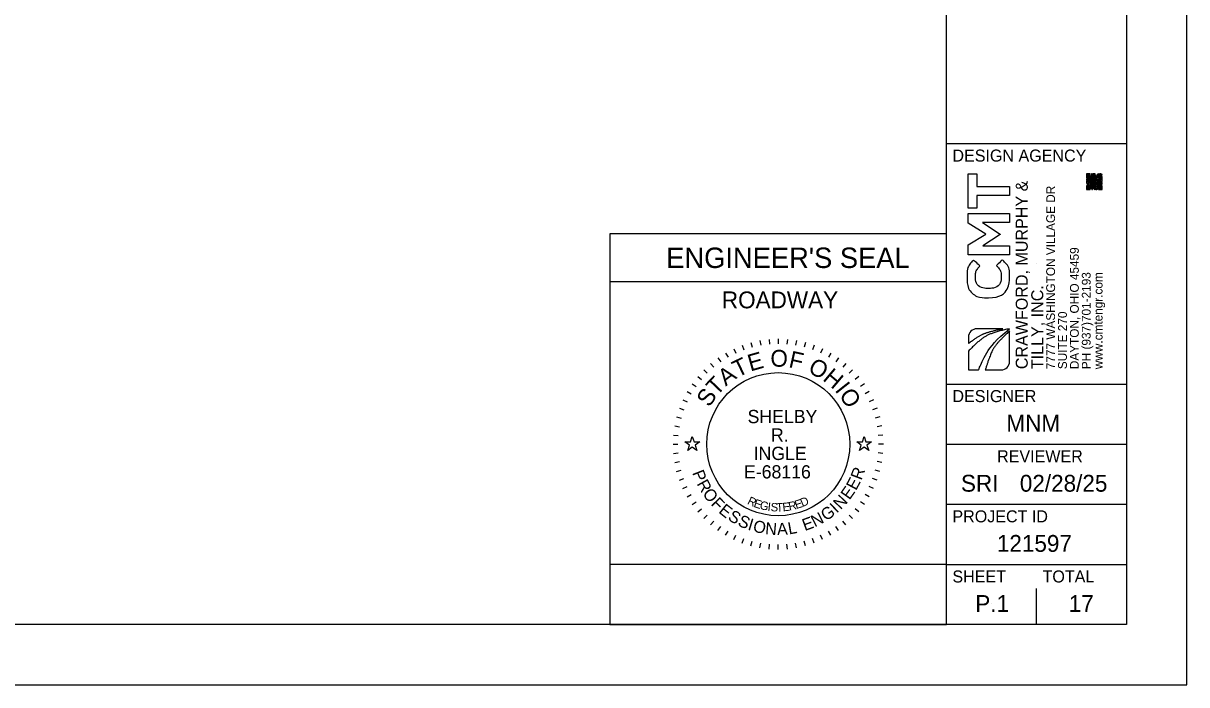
# Model space of a CAD drawing. Extents: x 0 to 42, y 0 to 22.
# Drawn here: x 24.32 to 34, y 0 to 5.5 of the extents above; entities that cross this region are included whole.
import ezdxf

# ---------------------------------------------------------------- set-up
doc = ezdxf.new("R2010")
doc.units = 0
for name, color, linetype in [('Default', 7, 'Continuous'), ('GM_X_Adjacent_County_Text', 7, 'Continuous'), ('GM_X_County', 7, 'Continuous'), ('GM_X_Minor_Lake', 7, 'Continuous'), ('GM_X_Section', 7, 'Continuous'), ('GM_X_Township', 7, 'Continuous')]:
    doc.layers.add(name, color=color, linetype=linetype)

msp = doc.modelspace()

# ---------------------------------------------------------------- linework, layer by layer
at = {"layer": 'Default'}
for points in [[(29.8236, 2.02), (29.8705, 2.02), (29.885, 2.0645), (29.8995, 2.02), (29.9464, 2.02), (29.9085, 1.9924), (29.923, 1.9478), (29.885, 1.9754), (29.847, 1.9478), (29.8615, 1.9924)], [(31.2536, 2.02), (31.3005, 2.02), (31.315, 2.0645), (31.3295, 2.02), (31.3764, 2.02), (31.3385, 1.9924), (31.353, 1.9478), (31.315, 1.9754), (31.277, 1.9478), (31.2915, 1.9924)]]:
    msp.add_lwpolyline(points, close=True, dxfattribs=at)
at = {"layer": 'GM_X_Adjacent_County_Text'}
for p, q in [((32.1822, 3.9637), (32.1822, 4.2476)), ((32.1822, 4.2476), (32.2517, 4.2476)), ((32.2517, 4.2476), (32.2517, 4.1434)), ((32.2517, 4.1434), (32.5248, 4.1434)), ((32.2517, 4.068), (32.2517, 3.9637)), ((32.5248, 4.068), (32.2517, 4.068)), ((32.5248, 4.1434), (32.5248, 4.068)), ((32.2517, 3.9637), (32.1822, 3.9637)), ((32.1822, 3.8368), (32.1822, 3.9181)), ((32.1822, 3.9181), (32.5248, 3.9181)), ((32.5248, 3.9181), (32.5248, 3.8432)), ((32.3271, 3.7467), (32.1822, 3.8368)), ((32.5248, 3.8432), (32.3012, 3.8432)), ((32.3012, 3.8432), (32.4475, 3.7467)), ((32.1822, 3.6567), (32.3271, 3.7467)), ((32.4475, 3.7448), (32.3026, 3.6493)), ((32.4475, 3.7467), (32.4475, 3.7448)), ((32.1822, 3.5754), (32.1822, 3.6567)), ((32.3026, 3.6493), (32.5248, 3.6493)), ((32.5248, 3.6493), (32.5248, 3.5754)), ((32.5248, 3.5754), (32.1822, 3.5754))]:
    msp.add_line(p, q, dxfattribs=at)
for points in [[(33.2836, 4.2433), (33.2791, 4.2433), (33.2791, 4.2387), (33.2745, 4.2387), (33.2745, 4.2297), (33.2655, 4.2297), (33.2655, 4.2342), (33.261, 4.2342), (33.261, 4.2387), (33.2519, 4.2387), (33.2519, 4.2252), (33.2564, 4.2252), (33.2564, 4.2206), (33.2474, 4.2206), (33.2474, 4.2161), (33.2519, 4.2161), (33.2519, 4.2116), (33.2383, 4.2116), (33.2383, 4.2206), (33.2338, 4.2206), (33.2338, 4.2252), (33.2383, 4.2252), (33.2383, 4.2206), (33.2474, 4.2206), (33.2474, 4.2252), (33.2429, 4.2252), (33.2429, 4.2342), (33.2293, 4.2342), (33.2293, 4.2387), (33.2247, 4.2387), (33.2247, 4.2433), (33.2293, 4.2433), (33.2293, 4.2387), (33.2338, 4.2387), (33.2338, 4.2433), (33.2383, 4.2433), (33.2383, 4.2478), (33.2157, 4.2478), (33.2157, 4.2433), (33.2202, 4.2433), (33.2202, 4.2297), (33.2293, 4.2297), (33.2293, 4.2252), (33.2157, 4.2252), (33.2157, 4.2206), (33.2247, 4.2206), (33.2247, 4.2161), (33.2338, 4.2161), (33.2338, 4.2116), (33.2293, 4.2116), (33.2293, 4.2071), (33.2247, 4.2071), (33.2247, 4.2161), (33.2202, 4.2161), (33.2202, 4.2116), (33.2157, 4.2116), (33.2157, 4.2071), (33.2202, 4.2071), (33.2202, 4.2025), (33.2112, 4.2025), (33.2112, 4.2116), (33.2066, 4.2116), (33.2066, 4.2071), (33.1976, 4.2071), (33.1976, 4.2025), (33.1931, 4.2025), (33.1931, 4.2071), (33.1976, 4.2071), (33.1976, 4.2116), (33.1885, 4.2116), (33.1885, 4.2071), (33.184, 4.2071), (33.184, 4.2116), (33.175, 4.2116), (33.175, 4.2025), (33.1704, 4.2025), (33.1704, 4.2071), (33.1659, 4.2071), (33.1659, 4.198), (33.1795, 4.198), (33.1795, 4.1844), (33.184, 4.1844), (33.184, 4.189), (33.1885, 4.189), (33.1885, 4.1935), (33.184, 4.1935), (33.184, 4.2025), (33.1885, 4.2025), (33.1885, 4.1935), (33.1931, 4.1935), (33.1931, 4.198), (33.1976, 4.198), (33.1976, 4.1935), (33.1931, 4.1935), (33.1931, 4.189), (33.2021, 4.189), (33.2021, 4.2025), (33.2066, 4.2025), (33.2066, 4.198), (33.2112, 4.198), (33.2112, 4.1935), (33.2157, 4.1935), (33.2157, 4.198), (33.2338, 4.198), (33.2338, 4.1935), (33.2383, 4.1935), (33.2383, 4.1844), (33.2338, 4.1844), (33.2338, 4.1799), (33.2519, 4.1799), (33.2519, 4.1844), (33.261, 4.1844), (33.261, 4.1799), (33.2519, 4.1799), (33.2519, 4.1709), (33.2564, 4.1709), (33.2564, 4.1618), (33.261, 4.1618), (33.261, 4.1663), (33.2655, 4.1663), (33.2655, 4.1754), (33.27, 4.1754), (33.27, 4.1573), (33.2791, 4.1573), (33.2791, 4.1663), (33.2745, 4.1663), (33.2745, 4.1709), (33.2791, 4.1709), (33.2791, 4.1663), (33.2836, 4.1663), (33.2836, 4.1573), (33.2791, 4.1573), (33.2791, 4.1528), (33.2881, 4.1528), (33.2881, 4.1618), (33.2972, 4.1618), (33.2972, 4.1709), (33.2926, 4.1709), (33.2926, 4.1663), (33.2881, 4.1663), (33.2881, 4.1754), (33.2791, 4.1754), (33.2791, 4.1799), (33.2836, 4.1799), (33.2836, 4.1844), (33.2972, 4.1844), (33.2972, 4.189), (33.2926, 4.189), (33.2926, 4.1935), (33.2972, 4.1935), (33.2972, 4.2116), (33.2836, 4.2116), (33.2836, 4.2071), (33.2926, 4.2071), (33.2926, 4.2025), (33.2836, 4.2025), (33.2836, 4.198), (33.2791, 4.198), (33.2791, 4.1935), (33.2745, 4.1935), (33.2745, 4.198), (33.27, 4.198), (33.27, 4.2071), (33.2791, 4.2071), (33.2791, 4.2252), (33.2836, 4.2252)], [(33.1976, 4.2478), (33.1659, 4.2478), (33.1659, 4.2161), (33.1976, 4.2161)], [(33.1795, 4.1844), (33.175, 4.1844), (33.175, 4.1935), (33.1659, 4.1935), (33.1659, 4.1709), (33.1704, 4.1709), (33.1704, 4.1663), (33.175, 4.1663), (33.175, 4.1618), (33.1704, 4.1618), (33.1704, 4.1573), (33.1795, 4.1573), (33.1795, 4.1618), (33.184, 4.1618), (33.184, 4.1799), (33.1795, 4.1799)], [(33.1931, 4.2433), (33.1931, 4.2206), (33.1704, 4.2206), (33.1704, 4.2433)], [(33.175, 4.1799), (33.175, 4.1754), (33.1704, 4.1754), (33.1704, 4.1799)], [(33.1885, 4.2387), (33.175, 4.2387), (33.175, 4.2252), (33.1885, 4.2252)], [(33.1931, 4.1799), (33.1885, 4.1799), (33.1885, 4.1754), (33.1931, 4.1754)], [(33.2021, 4.189), (33.2021, 4.1844), (33.1931, 4.1844), (33.1931, 4.1799), (33.1976, 4.1799), (33.1976, 4.1754), (33.2021, 4.1754), (33.2021, 4.1709), (33.1976, 4.1709), (33.1976, 4.1663), (33.2066, 4.1663), (33.2066, 4.1754), (33.2112, 4.1754), (33.2112, 4.1799), (33.2066, 4.1799), (33.2066, 4.189)], [(33.1931, 4.1754), (33.1931, 4.1709), (33.1976, 4.1709), (33.1976, 4.1754)], [(33.2066, 4.1663), (33.2066, 4.1618), (33.2021, 4.1618), (33.2021, 4.1573), (33.1931, 4.1573), (33.1931, 4.1528), (33.2021, 4.1528), (33.2021, 4.1437), (33.2066, 4.1437), (33.2066, 4.1573), (33.2112, 4.1573), (33.2112, 4.1618), (33.2157, 4.1618), (33.2157, 4.1663)], [(33.1976, 4.1663), (33.1931, 4.1663), (33.1931, 4.1618), (33.1976, 4.1618)], [(33.2157, 4.2433), (33.2112, 4.2433), (33.2112, 4.2387), (33.2066, 4.2387), (33.2066, 4.2297), (33.2021, 4.2297), (33.2021, 4.2252), (33.2066, 4.2252), (33.2066, 4.2206), (33.2021, 4.2206), (33.2021, 4.2116), (33.2066, 4.2116), (33.2066, 4.2161), (33.2157, 4.2161), (33.2157, 4.2206), (33.2112, 4.2206), (33.2112, 4.2252), (33.2157, 4.2252)], [(33.2112, 4.2433), (33.2112, 4.2478), (33.2066, 4.2478), (33.2066, 4.2433)], [(33.2112, 4.1799), (33.2157, 4.1799), (33.2157, 4.1754), (33.2202, 4.1754), (33.2202, 4.1573), (33.2293, 4.1573), (33.2293, 4.1528), (33.2338, 4.1528), (33.2338, 4.1618), (33.2247, 4.1618), (33.2247, 4.1663), (33.2338, 4.1663), (33.2338, 4.1709), (33.2293, 4.1709), (33.2293, 4.1754), (33.2247, 4.1754), (33.2247, 4.1799), (33.2202, 4.1799), (33.2202, 4.189), (33.2112, 4.189)], [(33.2247, 4.189), (33.2247, 4.1935), (33.2202, 4.1935), (33.2202, 4.189)], [(33.2338, 4.1844), (33.2338, 4.189), (33.2247, 4.189), (33.2247, 4.1799), (33.2293, 4.1799), (33.2293, 4.1844)], [(33.2338, 4.1799), (33.2293, 4.1799), (33.2293, 4.1754), (33.2338, 4.1754)], [(33.2338, 4.1709), (33.2429, 4.1709), (33.2429, 4.1663), (33.2519, 4.1663), (33.2519, 4.1709), (33.2474, 4.1709), (33.2474, 4.1754), (33.2338, 4.1754)], [(33.2655, 4.198), (33.2655, 4.1935), (33.27, 4.1935), (33.27, 4.189), (33.2791, 4.189), (33.2791, 4.1844), (33.2745, 4.1844), (33.2745, 4.1799), (33.27, 4.1799), (33.27, 4.1844), (33.2655, 4.1844), (33.2655, 4.189), (33.261, 4.189), (33.261, 4.1935), (33.2564, 4.1935), (33.2564, 4.198), (33.2519, 4.198), (33.2519, 4.1935), (33.2474, 4.1935), (33.2474, 4.189), (33.2429, 4.189), (33.2429, 4.198), (33.2383, 4.198), (33.2383, 4.2071), (33.2519, 4.2071), (33.2519, 4.2025), (33.261, 4.2025), (33.261, 4.198)], [(33.2429, 4.1663), (33.2383, 4.1663), (33.2383, 4.1618), (33.2429, 4.1618)], [(33.2519, 4.198), (33.2519, 4.2025), (33.2474, 4.2025), (33.2474, 4.198)], [(33.2655, 4.2342), (33.27, 4.2342), (33.27, 4.2433), (33.2655, 4.2433), (33.2655, 4.2478), (33.261, 4.2478), (33.261, 4.2387), (33.2655, 4.2387)], [(33.2745, 4.2252), (33.2745, 4.2116), (33.261, 4.2116), (33.261, 4.2252)], [(33.27, 4.2206), (33.2655, 4.2206), (33.2655, 4.2161), (33.27, 4.2161)], [(33.2791, 4.2433), (33.2791, 4.2478), (33.2745, 4.2478), (33.2745, 4.2433)], [(33.2791, 4.2025), (33.2745, 4.2025), (33.2745, 4.198), (33.2791, 4.198)], [(33.2836, 4.2071), (33.2791, 4.2071), (33.2791, 4.2025), (33.2836, 4.2025)], [(33.2881, 4.2433), (33.2881, 4.2478), (33.2836, 4.2478), (33.2836, 4.2433)], [(33.2836, 4.2252), (33.2836, 4.2206), (33.2881, 4.2206), (33.2881, 4.2252)], [(33.2972, 4.2387), (33.2972, 4.2433), (33.2881, 4.2433), (33.2881, 4.2387)], [(33.2926, 4.2252), (33.2926, 4.2342), (33.2881, 4.2342), (33.2881, 4.2252)], [(33.2881, 4.2206), (33.2881, 4.2161), (33.2972, 4.2161), (33.2972, 4.2252), (33.2926, 4.2252), (33.2926, 4.2206)], [(33.2881, 4.1754), (33.2972, 4.1754), (33.2972, 4.1799), (33.2881, 4.1799)], [(33.1976, 4.1482), (33.1659, 4.1482), (33.1659, 4.1166), (33.1976, 4.1166)], [(33.1931, 4.1437), (33.1931, 4.1211), (33.1704, 4.1211), (33.1704, 4.1437)], [(33.1885, 4.1256), (33.1885, 4.1392), (33.175, 4.1392), (33.175, 4.1256)], [(33.1885, 4.1528), (33.1885, 4.1573), (33.184, 4.1573), (33.184, 4.1528)], [(33.2112, 4.1347), (33.2021, 4.1347), (33.2021, 4.1256), (33.2112, 4.1256)], [(33.2293, 4.1528), (33.2202, 4.1528), (33.2202, 4.1392), (33.2157, 4.1392), (33.2157, 4.1482), (33.2112, 4.1482), (33.2112, 4.1347), (33.2202, 4.1347), (33.2202, 4.1256), (33.2247, 4.1256), (33.2247, 4.1301), (33.2383, 4.1301), (33.2383, 4.1347), (33.2429, 4.1347), (33.2429, 4.1301), (33.2519, 4.1301), (33.2519, 4.1256), (33.2564, 4.1256), (33.2564, 4.1211), (33.261, 4.1211), (33.261, 4.1301), (33.2564, 4.1301), (33.2564, 4.1392), (33.2519, 4.1392), (33.2519, 4.1482), (33.2564, 4.1482), (33.2564, 4.1437), (33.261, 4.1437), (33.261, 4.1528), (33.27, 4.1528), (33.27, 4.1573), (33.2564, 4.1573), (33.2564, 4.1528), (33.2519, 4.1528), (33.2519, 4.1573), (33.2474, 4.1573), (33.2474, 4.1528), (33.2429, 4.1528), (33.2429, 4.1573), (33.2383, 4.1573), (33.2383, 4.1528), (33.2338, 4.1528), (33.2338, 4.1482), (33.2383, 4.1482), (33.2383, 4.1437), (33.2429, 4.1437), (33.2429, 4.1482), (33.2474, 4.1482), (33.2474, 4.1392), (33.2338, 4.1392), (33.2338, 4.1347), (33.2247, 4.1347), (33.2247, 4.1392), (33.2338, 4.1392), (33.2338, 4.1482), (33.2293, 4.1482), (33.2293, 4.1437), (33.2247, 4.1437), (33.2247, 4.1482), (33.2293, 4.1482)], [(33.2112, 4.1256), (33.2112, 4.1166), (33.2157, 4.1166), (33.2157, 4.1256)], [(33.2338, 4.1211), (33.2338, 4.1256), (33.2293, 4.1256), (33.2293, 4.1211)], [(33.2383, 4.1211), (33.2338, 4.1211), (33.2338, 4.1166), (33.2383, 4.1166)], [(33.2383, 4.1301), (33.2383, 4.1211), (33.2429, 4.1211), (33.2429, 4.1301)], [(33.2519, 4.1166), (33.2519, 4.1211), (33.2474, 4.1211), (33.2474, 4.1166)], [(33.2972, 4.1482), (33.2655, 4.1482), (33.2655, 4.1166), (33.2972, 4.1166)], [(33.2926, 4.1437), (33.2926, 4.1211), (33.27, 4.1211), (33.27, 4.1437)], [(33.2881, 4.1392), (33.2745, 4.1392), (33.2745, 4.1256), (33.2881, 4.1256)]]:
    msp.add_lwpolyline(points, close=True, dxfattribs=at)
msp.add_open_spline([(32.3497, 3.2171), (32.3497, 3.2171), (32.3487, 3.2171), (32.3487, 3.2171), (32.2513, 3.2171), (32.1715, 3.2905), (32.1715, 3.3957), (32.1715, 3.4603), (32.1931, 3.499), (32.2244, 3.5308), (32.2244, 3.5308), (32.2797, 3.4829), (32.2797, 3.4829), (32.2557, 3.4564), (32.241, 3.4295), (32.241, 3.3952), (32.241, 3.3375), (32.289, 3.2959), (32.3478, 3.2959), (32.3478, 3.2959), (32.3487, 3.2959), (32.3487, 3.2959), (32.4075, 3.2959), (32.4564, 3.3365), (32.4564, 3.3952), (32.4564, 3.4344), (32.4408, 3.4584), (32.4163, 3.4853), (32.4163, 3.4853), (32.4647, 3.5333), (32.4647, 3.5333), (32.5024, 3.498), (32.5259, 3.4589), (32.5259, 3.3928), (32.5259, 3.292), (32.4481, 3.2171), (32.3497, 3.2171)], degree=3, dxfattribs=at)
at = {"layer": 'GM_X_County'}
for p, q in [((32, 0.5), (32, 21.5)), ((32, 4.5), (33.5, 4.5)), ((32, 2.5), (33.5, 2.5)), ((32, 2), (33.5, 2)), ((32, 1.5), (33.5, 1.5)), ((32, 1), (33.5, 1))]:
    msp.add_line(p, q, dxfattribs=at)
msp.add_lwpolyline([(1.5, 21.5), (33.5, 21.5), (33.5, 0.5), (1.5, 0.5)], close=True, dxfattribs=at)
at = {"layer": 'GM_X_Minor_Lake'}
for p, q in [((32.4705, 2.9599), (32.2543, 2.9599)), ((32.525, 2.9599), (32.5248, 2.9599)), ((32.5261, 2.6883), (32.5261, 2.9413)), ((32.1835, 2.8891), (32.1835, 2.8381)), ((32.1835, 2.7734), (32.1835, 2.6175)), ((32.1835, 2.6175), (32.2673, 2.6175)), ((32.3237, 2.6175), (32.4554, 2.6175))]:
    msp.add_line(p, q, dxfattribs=at)
msp.add_lwpolyline([(32.5261, 2.9413), (32.5261, 2.9413)], dxfattribs=at)
for centre, start, end in [((32.2543, 2.8891), 90, 180), ((32.4554, 2.6883), 270, 360)]:
    msp.add_arc(centre, 0.0708, start, end, dxfattribs=at)
for points, degree in [([(32.5248, 2.9599), (32.3926, 2.934), (32.2725, 2.8671), (32.1835, 2.7734)], 2), ([(32.1835, 2.8381), (32.2659, 2.9005), (32.3645, 2.9397), (32.4705, 2.9599)], 2), ([(32.2673, 2.6175), (32.2673, 2.6176), (32.2673, 2.6177), (32.2674, 2.6178), (32.3226, 2.7514), (32.4118, 2.8686), (32.525, 2.9599)], 3), ([(32.5261, 2.9413), (32.4344, 2.8571), (32.3669, 2.7609), (32.3237, 2.6175)], 2)]:
    msp.add_open_spline(points, degree=degree, dxfattribs=at)
at = {"layer": 'GM_X_Section'}
msp.add_lwpolyline([(0, 0), (34, 0), (34, 22), (0, 22)], close=True, dxfattribs=at)
at = {"layer": 'GM_X_Township'}
for p, q in [((32, 3.75), (29.2, 3.75)), ((29.2, 3.75), (29.2, 0.5)), ((32, 0.5), (32, 3.75)), ((32.75, 3.5), (32.75, 3.5)), ((32, 3.35), (29.2, 3.35)), ((30.3007, 2.8222), (30.3144, 2.7846)), ((30.3735, 2.8452), (30.3839, 2.8065)), ((30.4481, 2.8617), (30.455, 2.8223)), ((30.5237, 2.8717), (30.5272, 2.8318)), ((30.6, 2.875), (30.6, 2.835)), ((30.6763, 2.8717), (30.6728, 2.8318)), ((30.7519, 2.8617), (30.745, 2.8223)), ((30.8265, 2.8452), (30.8161, 2.8065)), ((30.8993, 2.8222), (30.8856, 2.7846)), ((30.0981, 2.7168), (30.1211, 2.684)), ((30.1625, 2.7578), (30.1825, 2.7231)), ((30.2302, 2.793), (30.2471, 2.7568)), ((30.9698, 2.793), (30.9529, 2.7568)), ((31.0375, 2.7578), (31.0175, 2.7231)), ((31.1019, 2.7168), (31.0789, 2.684)), ((29.9813, 2.6187), (30.0096, 2.5904)), ((30.0376, 2.6703), (30.0633, 2.6396)), ((31.1624, 2.6703), (31.1367, 2.6396)), ((31.2187, 2.6187), (31.1904, 2.5904)), ((29.9297, 2.5624), (29.9604, 2.5367)), ((31.2703, 2.5624), (31.2396, 2.5367)), ((29.8422, 2.4375), (29.8769, 2.4175)), ((29.8832, 2.5019), (29.916, 2.4789)), ((31.3168, 2.5019), (31.284, 2.4789)), ((31.3578, 2.4375), (31.3231, 2.4175)), ((29.807, 2.3698), (29.8432, 2.3529)), ((31.393, 2.3698), (31.3568, 2.3529)), ((29.7778, 2.2993), (29.8154, 2.2856)), ((31.4222, 2.2993), (31.3846, 2.2856)), ((29.7383, 2.1519), (29.7777, 2.145)), ((29.7548, 2.2265), (29.7935, 2.2161)), ((31.4452, 2.2265), (31.4065, 2.2161)), ((31.4617, 2.1519), (31.4223, 2.145)), ((29.7283, 2.0763), (29.7682, 2.0728)), ((31.4717, 2.0763), (31.4318, 2.0728)), ((29.725, 2), (29.765, 2)), ((31.475, 2), (31.435, 2)), ((29.7283, 1.9237), (29.7682, 1.9272)), ((29.7383, 1.8481), (29.7777, 1.855)), ((31.4617, 1.8481), (31.4223, 1.855)), ((31.4717, 1.9237), (31.4318, 1.9272)), ((29.7548, 1.7735), (29.7935, 1.7839)), ((31.4452, 1.7735), (31.4065, 1.7839)), ((29.7778, 1.7007), (29.8154, 1.7144)), ((29.807, 1.6302), (29.8432, 1.6471)), ((31.393, 1.6302), (31.3568, 1.6471)), ((31.4222, 1.7007), (31.3846, 1.7144)), ((29.8422, 1.5625), (29.8769, 1.5825)), ((31.3578, 1.5625), (31.3231, 1.5825)), ((29.8832, 1.4981), (29.916, 1.5211)), ((29.9297, 1.4376), (29.9604, 1.4633)), ((31.2703, 1.4376), (31.2396, 1.4633)), ((31.3168, 1.4981), (31.284, 1.5211)), ((29.9813, 1.3813), (30.0096, 1.4096)), ((30.0376, 1.3297), (30.0633, 1.3604)), ((31.1624, 1.3297), (31.1367, 1.3604)), ((31.2187, 1.3813), (31.1904, 1.4096)), ((30.0981, 1.2832), (30.1211, 1.316)), ((30.1625, 1.2422), (30.1825, 1.2769)), ((31.0375, 1.2422), (31.0175, 1.2769)), ((31.1019, 1.2832), (31.0789, 1.316)), ((30.2302, 1.207), (30.2471, 1.2432)), ((30.3007, 1.1778), (30.3144, 1.2154)), ((30.3735, 1.1548), (30.3839, 1.1935)), ((30.4481, 1.1383), (30.455, 1.1777)), ((30.5237, 1.1283), (30.5272, 1.1682)), ((30.6, 1.125), (30.6, 1.165)), ((30.6763, 1.1283), (30.6728, 1.1682)), ((30.7519, 1.1383), (30.745, 1.1777)), ((30.8265, 1.1548), (30.8161, 1.1935)), ((30.8993, 1.1778), (30.8856, 1.2154)), ((30.9698, 1.207), (30.9529, 1.2432)), ((32.75, 0.5), (32.75, 0.8)), ((32.375, 0.675), (32.375, 0.675)), ((32, 0.5), (29.2, 0.5))]:
    msp.add_line(p, q, dxfattribs=at)
msp.add_lwpolyline([(32, 0.5), (32, 1), (29.2, 1), (29.2, 0.5)], close=True, dxfattribs=at)
msp.add_circle((30.6, 2), 0.595, dxfattribs=at)

# ---------------------------------------------------------------- texts
at = {"layer": 'GM_X_Adjacent_County_Text'}
for s, height, p in [('CRAWFORD, MURPHY &', 0.1, (32.6768, 2.6238)), ('7777 WASHINGTON VILLAGE DR', 0.073313, (32.904, 2.6238)), ('DAYTON, OHIO 45459', 0.073313, (33.1016, 2.6238)), ('PH (937)701-2193', 0.073313, (33.2004, 2.6238)), ('www.cmtengr.com', 0.073313, (33.2991, 2.6238)), ('TILLY, INC.', 0.1, (32.8062, 2.6238)), ('SUITE 270', 0.07331, (33.0028, 2.6238))]:
    msp.add_text(s, height=height, rotation=90, dxfattribs=at).set_placement(p)
at = {"layer": 'GM_X_Township'}
for s, height, p in [('DESIGN AGENCY', 0.1, (32.05, 4.35)), ("ENGINEER'S SEAL", 0.17, (29.6676, 3.465)), ('ROADWAY', 0.14, (30.1311, 3.13)), ('DESIGNER', 0.1, (32.05, 2.35)), ('SHELBY', 0.11, (30.3451, 2.1749)), ('MNM', 0.14, (32.4994, 2.105)), ('R.', 0.11, (30.5397, 2.0216)), ('INGLE', 0.11, (30.3954, 1.8684)), ('REVIEWER', 0.1, (32.4218, 1.85)), ('E-68116', 0.11, (30.3154, 1.7151)), ('SRI', 0.14, (32.1209, 1.605)), ('02/28/25', 0.14, (32.611, 1.605)), ('PROJECT ID', 0.1, (32.05, 1.35)), ('121597', 0.14, (32.4198, 1.105)), ('SHEET', 0.1, (32.05, 0.85)), ('TOTAL', 0.1, (32.8, 0.85)), ('P.1', 0.14, (32.2403, 0.605)), ('17', 0.14, (33.0183, 0.605))]:
    msp.add_text(s, height=height, dxfattribs=at).set_placement(p)
for s, height, rotation, p in [('T', 0.14, 25.71674, (30.2616, 2.5518)), ('E', 0.14, 15.75706, (30.3684, 2.6038)), ('O', 0.14, 359.78119, (30.5347, 2.6443)), ('F', 0.14, 347.43619, (30.6811, 2.6417)), ('A', 0.14, 36.47472, (30.1634, 2.4781)), ('O', 0.14, 332.25863, (30.8398, 2.6015)), ('H', 0.14, 319.91363, (30.9632, 2.5361)), ('T', 0.14, 46.4344, (30.0883, 2.3964)), ('I', 0.14, 308.36695, (31.0665, 2.4483)), ('S', 0.14, 57.19238, (30.0281, 2.3014)), ('O', 0.14, 303.14906, (31.1021, 2.4089)), ('P', 0.1, 291.49398, (29.8823, 1.7621)), ('R', 0.1, 69.23216, (31.2919, 1.6954)), ('R', 0.1, 298.73106, (29.919, 1.6717)), ('E', 0.1, 54.75801, (31.1933, 1.5314)), ('E', 0.1, 61.99508, (31.2476, 1.6098)), ('O', 0.1, 306.46664, (29.9655, 1.5883)), ('F', 0.1, 314.7068, (30.0343, 1.4983)), ('R', 0.07, 334.48695, (30.3375, 1.5051)), ('D', 0.07, 23.30524, (30.801, 1.477)), ('N', 0.1, 47.02243, (31.1202, 1.4508)), ('E', 0.1, 321.43929, (30.0978, 1.4348)), ('E', 0.07, 341.03996, (30.3906, 1.4801)), ('G', 0.07, 347.47515, (30.4414, 1.4618)), ('I', 0.07, 353.78581, (30.5091, 1.4468)), ('S', 0.07, 356.89262, (30.5358, 1.4429)), ('T', 0.07, 3.00609, (30.5857, 1.4387)), ('E', 0.07, 6.01169, (30.6389, 1.4412)), ('R', 0.07, 11.91844, (30.6925, 1.4474)), ('E', 0.07, 17.68363, (30.7498, 1.4602)), ('G', 0.1, 35.04687, (30.9981, 1.357)), ('I', 0.1, 43.28703, (31.0868, 1.4214)), ('S', 0.1, 328.67637, (30.1743, 1.3752)), ('S', 0.1, 335.91345, (30.2564, 1.3266)), ('I', 0.1, 343.15053, (30.3406, 1.2897)), ('O', 0.1, 346.88592, (30.3839, 1.2751)), ('E', 0.1, 20.07421, (30.8212, 1.277)), ('N', 0.1, 27.31129, (30.9045, 1.3075)), ('N', 0.1, 355.12608, (30.4888, 1.2517)), ('A', 0.1, 2.86166, (30.5923, 1.2437)), ('L', 0.1, 10.09874, (30.6894, 1.249))]:
    msp.add_text(s, height=height, rotation=rotation, dxfattribs=at).set_placement(p)

doc.saveas('drawing.dxf')
